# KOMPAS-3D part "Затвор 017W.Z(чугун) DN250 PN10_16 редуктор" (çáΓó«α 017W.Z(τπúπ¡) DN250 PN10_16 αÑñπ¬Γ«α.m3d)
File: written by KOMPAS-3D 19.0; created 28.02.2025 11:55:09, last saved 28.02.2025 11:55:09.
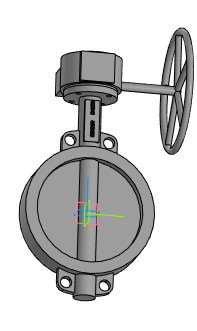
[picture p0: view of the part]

Document properties: Автор: Евгений; Полное имя файла: Затвор 017W.Z(чугун) DN250 PN10_16 редуктор.a3d

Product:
- Part/product: Затвор 017W.Z(чугун) DN250 PN10_16 редуктор
    Масса: 42.0906

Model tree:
1. Операция без истории:1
